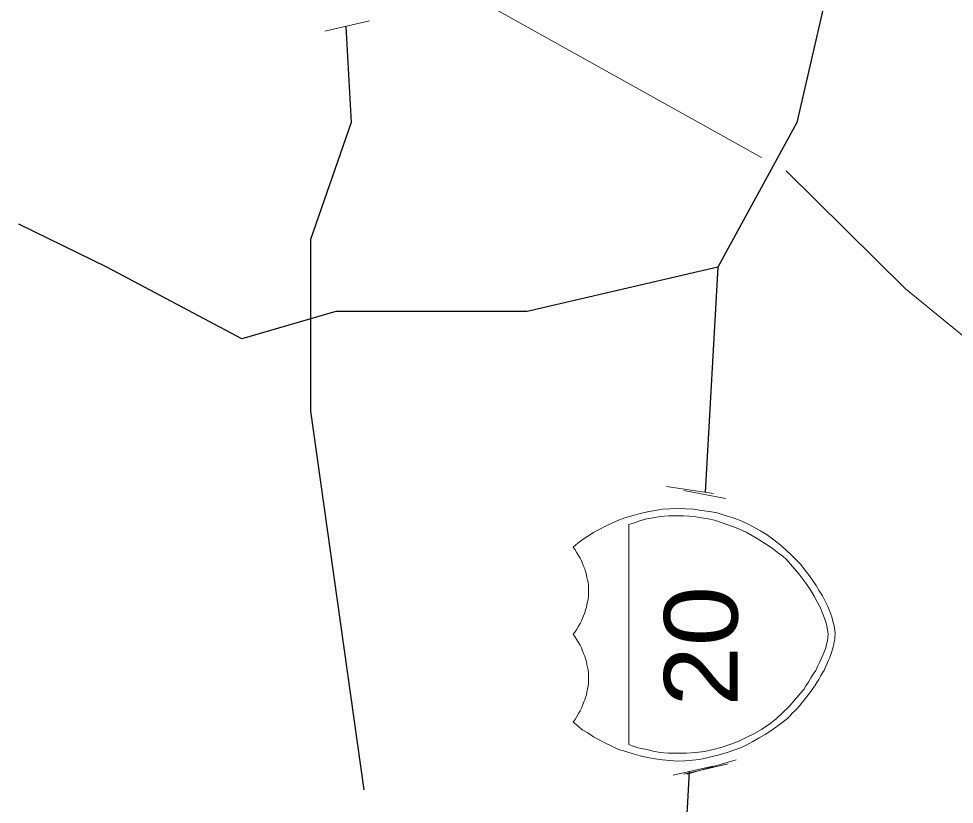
# Model space of a CAD drawing. Extents: x 2363323 to 2367082, y 6956018 to 6980837.
# Drawn here: x 2366011.6 to 2366076.4, y 6956720 to 6956774.4 of the extents above; entities that cross this region are included whole.
import ezdxf

# ---------------------------------------------------------------- set-up
doc = ezdxf.new("R2010")
doc.units = 0
doc.header["$LTSCALE"] = 4.1
doc.layers.add('62', color=7, linetype='Continuous', lineweight=13)
doc.layers.add('63', color=7, linetype='Continuous', lineweight=13)

msp = doc.modelspace()

# ---------------------------------------------------------------- linework, layer by layer
at = {"layer": '62'}
for p, q in [((2366041.733, 6956776.678), (2366062.997, 6956764.818)), ((2366032.779, 6956773.574), (2366035.861, 6956774.27)), ((2366056.431, 6956742.046), (2366059.691, 6956741.552)), ((2366057.621, 6956741.775), (2366060.524, 6956741.214)), ((2366057.869, 6956722.132), (2366061.244, 6956723.122)), ((2366056.881, 6956722.065), (2366059.647, 6956722.674)), ((2366057.623, 6956722.134), (2366060.705, 6956722.83))]:
    msp.add_line(p, q, dxfattribs=at)
at = {"layer": '62', "lineweight": 25}
for p, q in [((2366017.681, 6956757.237), (2366011.581, 6956760.206)), ((2366059.984, 6956757.237), (2366059.108, 6956741.642))]:
    msp.add_line(p, q, dxfattribs=at)
for points in [[(2366063.045, 6956932.21), (2366064.574, 6956924.38), (2366065.453, 6956914.39), (2366066.511, 6956900.348), (2366066.509, 6956890.358), (2366067.387, 6956883.202), (2366070.199, 6956878.208), (2366072.157, 6956868.194), (2366071.099, 6956854.152), (2366070.199, 6956841.303), (2366069.344, 6956827.239), (2366072.158, 6956805.098), (2366069.344, 6956784.148), (2366065.451, 6956767.248), (2366059.984, 6956757.237), (2366046.773, 6956754.154), (2366033.545, 6956754.153), (2366027.019, 6956752.263), (2366017.681, 6956757.237)], [(2366034.219, 6956773.887), (2366034.603, 6956767.248), (2366031.79, 6956759.148), (2366031.789, 6956747.246), (2366035.48, 6956721.052)], [(2366058.005, 6956722.312), (2366057.218, 6956708.001), (2366049.586, 6956693.352), (2366037.369, 6956685.456)]]:
    msp.add_lwpolyline(points, dxfattribs=at)
at = {"layer": '62'}
for points in [[(2366064.711, 6956763.894), (2366072.967, 6956755.728), (2366080.301, 6956749.743), (2366092.906, 6956736.826), (2366106.337, 6956725.194)], [(2366050.443, 6956732.55), (2366050.533, 6956732.73), (2366050.623, 6956732.932), (2366050.69, 6956733.09), (2366050.78, 6956733.294), (2366050.825, 6956733.495), (2366050.894, 6956733.675), (2366050.915, 6956733.855), (2366050.96, 6956734.056), (2366051.007, 6956734.238), (2366051.029, 6956734.438), (2366051.029, 6956734.62), (2366051.027, 6956734.824), (2366051.027, 6956735.004), (2366051.027, 6956735.184), (2366051.005, 6956735.409), (2366050.961, 6956735.566), (2366050.915, 6956735.746), (2366050.893, 6956735.95), (2366050.825, 6956736.152), (2366050.78, 6956736.333), (2366050.691, 6956736.534), (2366050.624, 6956736.714), (2366050.534, 6956736.892), (2366050.443, 6956737.076), (2366050.329, 6956737.254), (2366050.217, 6956737.456), (2366050.103, 6956737.66), (2366049.969, 6956737.84), (2366050.283, 6956738.109), (2366050.601, 6956738.356), (2366050.983, 6956738.604), (2366051.365, 6956738.852), (2366051.773, 6956739.075), (2366052.199, 6956739.302), (2366052.649, 6956739.504), (2366053.099, 6956739.706), (2366053.617, 6956739.886), (2366054.111, 6956740.042), (2366054.608, 6956740.18), (2366055.124, 6956740.292), (2366055.643, 6956740.382), (2366056.159, 6956740.472), (2366056.654, 6956740.494), (2366057.194, 6956740.539), (2366057.735, 6956740.494), (2366058.319, 6956740.472), (2366058.861, 6956740.382), (2366059.399, 6956740.314), (2366059.939, 6956740.226), (2366060.479, 6956740.044), (2366060.974, 6956739.886), (2366061.491, 6956739.706), (2366061.988, 6956739.482), (2366062.481, 6956739.234), (2366062.931, 6956738.966), (2366063.405, 6956738.694), (2366063.855, 6956738.358), (2366064.281, 6956738.019), (2366064.687, 6956737.659), (2366065.114, 6956737.254), (2366065.407, 6956736.962), (2366065.721, 6956736.646), (2366065.991, 6956736.286), (2366066.261, 6956735.95), (2366066.531, 6956735.566), (2366066.779, 6956735.182), (2366067.005, 6956734.824), (2366067.231, 6956734.462), (2366067.409, 6956734.102), (2366067.589, 6956733.742), (2366067.747, 6956733.382), (2366067.881, 6956733.024), (2366067.949, 6956732.708), (2366068.041, 6956732.392), (2366068.084, 6956732.078), (2366068.107, 6956731.809)], [(2366068.107, 6956731.809), (2366068.085, 6956731.626), (2366068.085, 6956731.47), (2366068.039, 6956731.29), (2366068.017, 6956731.134), (2366067.971, 6956730.952), (2366067.927, 6956730.772), (2366067.859, 6956730.548), (2366067.791, 6956730.345), (2366067.703, 6956730.166), (2366067.613, 6956729.962), (2366067.521, 6956729.738), (2366067.431, 6956729.535), (2366067.341, 6956729.31), (2366067.231, 6956729.132), (2366067.095, 6956728.905), (2366066.981, 6956728.68), (2366066.847, 6956728.478), (2366066.689, 6956728.252), (2366066.555, 6956728.052), (2366066.421, 6956727.849), (2366066.263, 6956727.645), (2366066.104, 6956727.444), (2366065.948, 6956727.24), (2366065.791, 6956727.06), (2366065.631, 6956726.858), (2366065.474, 6956726.678), (2366065.294, 6956726.498), (2366065.137, 6956726.34), (2366064.957, 6956726.138), (2366064.801, 6956725.98), (2366064.619, 6956725.845), (2366064.417, 6956725.688), (2366064.057, 6956725.416), (2366063.651, 6956725.125), (2366063.248, 6956724.878), (2366062.843, 6956724.63), (2366062.415, 6956724.384), (2366061.988, 6956724.158), (2366061.559, 6956723.956), (2366061.087, 6956723.798), (2366060.637, 6956723.618), (2366060.165, 6956723.482), (2366059.691, 6956723.37), (2366059.219, 6956723.258), (2366058.724, 6956723.145), (2366058.231, 6956723.1), (2366057.689, 6956723.054), (2366057.195, 6956723.034), (2366056.653, 6956723.078), (2366056.159, 6956723.124), (2366055.641, 6956723.19), (2366055.124, 6956723.282), (2366054.608, 6956723.392), (2366054.111, 6956723.526), (2366053.617, 6956723.684), (2366053.099, 6956723.844), (2366052.651, 6956724.068), (2366052.199, 6956724.272), (2366051.773, 6956724.495), (2366051.365, 6956724.72), (2366050.983, 6956724.988), (2366050.6, 6956725.192), (2366050.285, 6956725.461), (2366049.969, 6956725.732), (2366050.103, 6956725.912), (2366050.217, 6956726.115), (2366050.329, 6956726.318), (2366050.443, 6956726.499), (2366050.533, 6956726.7), (2366050.623, 6956726.88), (2366050.691, 6956727.082), (2366050.78, 6956727.264), (2366050.825, 6956727.442), (2366050.893, 6956727.622), (2366050.915, 6956727.825), (2366050.961, 6956728.005), (2366051.005, 6956728.232), (2366051.027, 6956728.388), (2366051.027, 6956728.568), (2366051.029, 6956728.794), (2366051.027, 6956728.974), (2366051.029, 6956729.151), (2366051.007, 6956729.355), (2366050.961, 6956729.535), (2366050.917, 6956729.714), (2366050.893, 6956729.895), (2366050.827, 6956730.122), (2366050.781, 6956730.302), (2366050.69, 6956730.48), (2366050.624, 6956730.66), (2366050.533, 6956730.862), (2366050.443, 6956731.065), (2366050.329, 6956731.246), (2366050.216, 6956731.425), (2366050.105, 6956731.605), (2366049.969, 6956731.808), (2366050.105, 6956731.988), (2366050.217, 6956732.168), (2366050.33, 6956732.37), (2366050.443, 6956732.55)]]:
    msp.add_lwpolyline(points, dxfattribs=at)
msp.add_lwpolyline([(2366053.821, 6956739.414), (2366053.821, 6956724.18), (2366054.045, 6956724.09), (2366054.337, 6956724), (2366054.653, 6956723.91), (2366055.058, 6956723.822), (2366055.508, 6956723.708), (2366056.001, 6956723.618), (2366056.565, 6956723.574), (2366057.195, 6956723.572), (2366057.803, 6956723.572), (2366058.431, 6956723.618), (2366059.061, 6956723.706), (2366059.669, 6956723.844), (2366060.277, 6956724), (2366060.818, 6956724.18), (2366061.401, 6956724.384), (2366061.943, 6956724.654), (2366062.481, 6956724.922), (2366062.999, 6956725.215), (2366063.518, 6956725.575), (2366063.991, 6956725.935), (2366064.461, 6956726.362), (2366064.911, 6956726.812), (2366065.318, 6956727.262), (2366065.723, 6956727.758), (2366065.925, 6956727.982), (2366066.081, 6956728.252), (2366066.263, 6956728.5), (2366066.421, 6956728.791), (2366066.577, 6956729.04), (2366066.758, 6956729.31), (2366066.891, 6956729.582), (2366067.027, 6956729.85), (2366067.139, 6956730.12), (2366067.251, 6956730.368), (2366067.365, 6956730.639), (2366067.454, 6956730.862), (2366067.499, 6956731.132), (2366067.568, 6956731.356), (2366067.591, 6956731.582), (2366067.611, 6956731.809), (2366067.568, 6956732.122), (2366067.499, 6956732.505), (2366067.388, 6956732.866), (2366067.231, 6956733.27), (2366067.095, 6956733.652), (2366066.869, 6956734.056), (2366066.644, 6956734.44), (2366066.421, 6956734.846), (2366066.149, 6956735.252), (2366065.857, 6956735.636), (2366065.588, 6956735.994), (2366065.294, 6956736.332), (2366065.024, 6956736.67), (2366064.755, 6956736.962), (2366064.461, 6956737.232), (2366064.214, 6956737.412), (2366063.741, 6956737.772), (2366063.291, 6956738.064), (2366062.843, 6956738.356), (2366062.371, 6956738.625), (2366061.943, 6956738.876), (2366061.491, 6956739.078), (2366061.065, 6956739.256), (2366060.615, 6956739.416), (2366060.165, 6956739.572), (2366059.761, 6956739.706), (2366059.309, 6956739.796), (2366058.881, 6956739.864), (2366058.454, 6956739.932), (2366058.027, 6956739.976), (2366057.601, 6956739.999), (2366057.194, 6956739.999), (2366056.565, 6956739.999), (2366056.001, 6956739.954), (2366055.508, 6956739.864), (2366055.058, 6956739.796), (2366054.653, 6956739.684), (2366054.338, 6956739.572), (2366054.044, 6956739.482)], close=True, dxfattribs=at)
at = {"layer": '63'}
for p, q in [((2366041.733, 6956776.678), (2366062.997, 6956764.818)), ((2366032.779, 6956773.574), (2366035.861, 6956774.27)), ((2366056.431, 6956742.046), (2366059.691, 6956741.552)), ((2366057.621, 6956741.775), (2366060.524, 6956741.214)), ((2366057.869, 6956722.132), (2366061.244, 6956723.122)), ((2366056.881, 6956722.065), (2366059.647, 6956722.674)), ((2366057.623, 6956722.134), (2366060.705, 6956722.83))]:
    msp.add_line(p, q, dxfattribs=at)
at = {"layer": '63', "lineweight": 25}
for p, q in [((2366017.681, 6956757.237), (2366011.581, 6956760.206)), ((2366059.984, 6956757.237), (2366059.108, 6956741.642))]:
    msp.add_line(p, q, dxfattribs=at)
for points in [[(2366063.045, 6956932.21), (2366064.574, 6956924.38), (2366065.453, 6956914.39), (2366066.511, 6956900.348), (2366066.509, 6956890.358), (2366067.387, 6956883.202), (2366070.199, 6956878.208), (2366072.157, 6956868.194), (2366071.099, 6956854.152), (2366070.199, 6956841.303), (2366069.344, 6956827.239), (2366072.158, 6956805.098), (2366069.344, 6956784.148), (2366065.451, 6956767.248), (2366059.984, 6956757.237), (2366046.773, 6956754.154), (2366033.545, 6956754.153), (2366027.019, 6956752.263), (2366017.681, 6956757.237)], [(2366034.219, 6956773.887), (2366034.603, 6956767.248), (2366031.79, 6956759.148), (2366031.789, 6956747.246), (2366035.48, 6956721.052)], [(2366058.005, 6956722.312), (2366057.218, 6956708.001), (2366049.586, 6956693.352), (2366037.369, 6956685.456)]]:
    msp.add_lwpolyline(points, dxfattribs=at)
at = {"layer": '63'}
for points in [[(2366064.711, 6956763.894), (2366072.967, 6956755.728), (2366080.301, 6956749.743), (2366092.906, 6956736.826), (2366106.337, 6956725.194)], [(2366050.443, 6956732.55), (2366050.533, 6956732.73), (2366050.623, 6956732.932), (2366050.69, 6956733.09), (2366050.78, 6956733.294), (2366050.825, 6956733.495), (2366050.894, 6956733.675), (2366050.915, 6956733.855), (2366050.96, 6956734.056), (2366051.007, 6956734.238), (2366051.029, 6956734.438), (2366051.029, 6956734.62), (2366051.027, 6956734.824), (2366051.027, 6956735.004), (2366051.027, 6956735.184), (2366051.005, 6956735.409), (2366050.961, 6956735.566), (2366050.915, 6956735.746), (2366050.893, 6956735.95), (2366050.825, 6956736.152), (2366050.78, 6956736.333), (2366050.691, 6956736.534), (2366050.624, 6956736.714), (2366050.534, 6956736.892), (2366050.443, 6956737.076), (2366050.329, 6956737.254), (2366050.217, 6956737.456), (2366050.103, 6956737.66), (2366049.969, 6956737.84), (2366050.283, 6956738.109), (2366050.601, 6956738.356), (2366050.983, 6956738.604), (2366051.365, 6956738.852), (2366051.773, 6956739.075), (2366052.199, 6956739.302), (2366052.649, 6956739.504), (2366053.099, 6956739.706), (2366053.617, 6956739.886), (2366054.111, 6956740.042), (2366054.608, 6956740.18), (2366055.124, 6956740.292), (2366055.643, 6956740.382), (2366056.159, 6956740.472), (2366056.654, 6956740.494), (2366057.194, 6956740.539), (2366057.735, 6956740.494), (2366058.319, 6956740.472), (2366058.861, 6956740.382), (2366059.399, 6956740.314), (2366059.939, 6956740.226), (2366060.479, 6956740.044), (2366060.974, 6956739.886), (2366061.491, 6956739.706), (2366061.988, 6956739.482), (2366062.481, 6956739.234), (2366062.931, 6956738.966), (2366063.405, 6956738.694), (2366063.855, 6956738.358), (2366064.281, 6956738.019), (2366064.687, 6956737.659), (2366065.114, 6956737.254), (2366065.407, 6956736.962), (2366065.721, 6956736.646), (2366065.991, 6956736.286), (2366066.261, 6956735.95), (2366066.531, 6956735.566), (2366066.779, 6956735.182), (2366067.005, 6956734.824), (2366067.231, 6956734.462), (2366067.409, 6956734.102), (2366067.589, 6956733.742), (2366067.747, 6956733.382), (2366067.881, 6956733.024), (2366067.949, 6956732.708), (2366068.041, 6956732.392), (2366068.084, 6956732.078), (2366068.107, 6956731.809)], [(2366068.107, 6956731.809), (2366068.085, 6956731.626), (2366068.085, 6956731.47), (2366068.039, 6956731.29), (2366068.017, 6956731.134), (2366067.971, 6956730.952), (2366067.927, 6956730.772), (2366067.859, 6956730.548), (2366067.791, 6956730.345), (2366067.703, 6956730.166), (2366067.613, 6956729.962), (2366067.521, 6956729.738), (2366067.431, 6956729.535), (2366067.341, 6956729.31), (2366067.231, 6956729.132), (2366067.095, 6956728.905), (2366066.981, 6956728.68), (2366066.847, 6956728.478), (2366066.689, 6956728.252), (2366066.555, 6956728.052), (2366066.421, 6956727.849), (2366066.263, 6956727.645), (2366066.104, 6956727.444), (2366065.948, 6956727.24), (2366065.791, 6956727.06), (2366065.631, 6956726.858), (2366065.474, 6956726.678), (2366065.294, 6956726.498), (2366065.137, 6956726.34), (2366064.957, 6956726.138), (2366064.801, 6956725.98), (2366064.619, 6956725.845), (2366064.417, 6956725.688), (2366064.057, 6956725.416), (2366063.651, 6956725.125), (2366063.248, 6956724.878), (2366062.843, 6956724.63), (2366062.415, 6956724.384), (2366061.988, 6956724.158), (2366061.559, 6956723.956), (2366061.087, 6956723.798), (2366060.637, 6956723.618), (2366060.165, 6956723.482), (2366059.691, 6956723.37), (2366059.219, 6956723.258), (2366058.724, 6956723.145), (2366058.231, 6956723.1), (2366057.689, 6956723.054), (2366057.195, 6956723.034), (2366056.653, 6956723.078), (2366056.159, 6956723.124), (2366055.641, 6956723.19), (2366055.124, 6956723.282), (2366054.608, 6956723.392), (2366054.111, 6956723.526), (2366053.617, 6956723.684), (2366053.099, 6956723.844), (2366052.651, 6956724.068), (2366052.199, 6956724.272), (2366051.773, 6956724.495), (2366051.365, 6956724.72), (2366050.983, 6956724.988), (2366050.6, 6956725.192), (2366050.285, 6956725.461), (2366049.969, 6956725.732), (2366050.103, 6956725.912), (2366050.217, 6956726.115), (2366050.329, 6956726.318), (2366050.443, 6956726.499), (2366050.533, 6956726.7), (2366050.623, 6956726.88), (2366050.691, 6956727.082), (2366050.78, 6956727.264), (2366050.825, 6956727.442), (2366050.893, 6956727.622), (2366050.915, 6956727.825), (2366050.961, 6956728.005), (2366051.005, 6956728.232), (2366051.027, 6956728.388), (2366051.027, 6956728.568), (2366051.029, 6956728.794), (2366051.027, 6956728.974), (2366051.029, 6956729.151), (2366051.007, 6956729.355), (2366050.961, 6956729.535), (2366050.917, 6956729.714), (2366050.893, 6956729.895), (2366050.827, 6956730.122), (2366050.781, 6956730.302), (2366050.69, 6956730.48), (2366050.624, 6956730.66), (2366050.533, 6956730.862), (2366050.443, 6956731.065), (2366050.329, 6956731.246), (2366050.216, 6956731.425), (2366050.105, 6956731.605), (2366049.969, 6956731.808), (2366050.105, 6956731.988), (2366050.217, 6956732.168), (2366050.33, 6956732.37), (2366050.443, 6956732.55)]]:
    msp.add_lwpolyline(points, dxfattribs=at)
msp.add_lwpolyline([(2366053.821, 6956739.414), (2366053.821, 6956724.18), (2366054.045, 6956724.09), (2366054.337, 6956724), (2366054.653, 6956723.91), (2366055.058, 6956723.822), (2366055.508, 6956723.708), (2366056.001, 6956723.618), (2366056.565, 6956723.574), (2366057.195, 6956723.572), (2366057.803, 6956723.572), (2366058.431, 6956723.618), (2366059.061, 6956723.706), (2366059.669, 6956723.844), (2366060.277, 6956724), (2366060.818, 6956724.18), (2366061.401, 6956724.384), (2366061.943, 6956724.654), (2366062.481, 6956724.922), (2366062.999, 6956725.215), (2366063.518, 6956725.575), (2366063.991, 6956725.935), (2366064.461, 6956726.362), (2366064.911, 6956726.812), (2366065.318, 6956727.262), (2366065.723, 6956727.758), (2366065.925, 6956727.982), (2366066.081, 6956728.252), (2366066.263, 6956728.5), (2366066.421, 6956728.791), (2366066.577, 6956729.04), (2366066.758, 6956729.31), (2366066.891, 6956729.582), (2366067.027, 6956729.85), (2366067.139, 6956730.12), (2366067.251, 6956730.368), (2366067.365, 6956730.639), (2366067.454, 6956730.862), (2366067.499, 6956731.132), (2366067.568, 6956731.356), (2366067.591, 6956731.582), (2366067.611, 6956731.809), (2366067.568, 6956732.122), (2366067.499, 6956732.505), (2366067.388, 6956732.866), (2366067.231, 6956733.27), (2366067.095, 6956733.652), (2366066.869, 6956734.056), (2366066.644, 6956734.44), (2366066.421, 6956734.846), (2366066.149, 6956735.252), (2366065.857, 6956735.636), (2366065.588, 6956735.994), (2366065.294, 6956736.332), (2366065.024, 6956736.67), (2366064.755, 6956736.962), (2366064.461, 6956737.232), (2366064.214, 6956737.412), (2366063.741, 6956737.772), (2366063.291, 6956738.064), (2366062.843, 6956738.356), (2366062.371, 6956738.625), (2366061.943, 6956738.876), (2366061.491, 6956739.078), (2366061.065, 6956739.256), (2366060.615, 6956739.416), (2366060.165, 6956739.572), (2366059.761, 6956739.706), (2366059.309, 6956739.796), (2366058.881, 6956739.864), (2366058.454, 6956739.932), (2366058.027, 6956739.976), (2366057.601, 6956739.999), (2366057.194, 6956739.999), (2366056.565, 6956739.999), (2366056.001, 6956739.954), (2366055.508, 6956739.864), (2366055.058, 6956739.796), (2366054.653, 6956739.684), (2366054.338, 6956739.572), (2366054.044, 6956739.482)], close=True, dxfattribs=at)

# ---------------------------------------------------------------- texts
at = {"layer": '62', "width": 1.1}
msp.add_text('20', height=5.099, rotation=90, dxfattribs=at).set_placement((2366061.356, 6956726.813))
at = {"layer": '63', "width": 1.1}
msp.add_text('20', height=5.099, rotation=90, dxfattribs=at).set_placement((2366061.356, 6956726.813))

doc.saveas('drawing.dxf')
